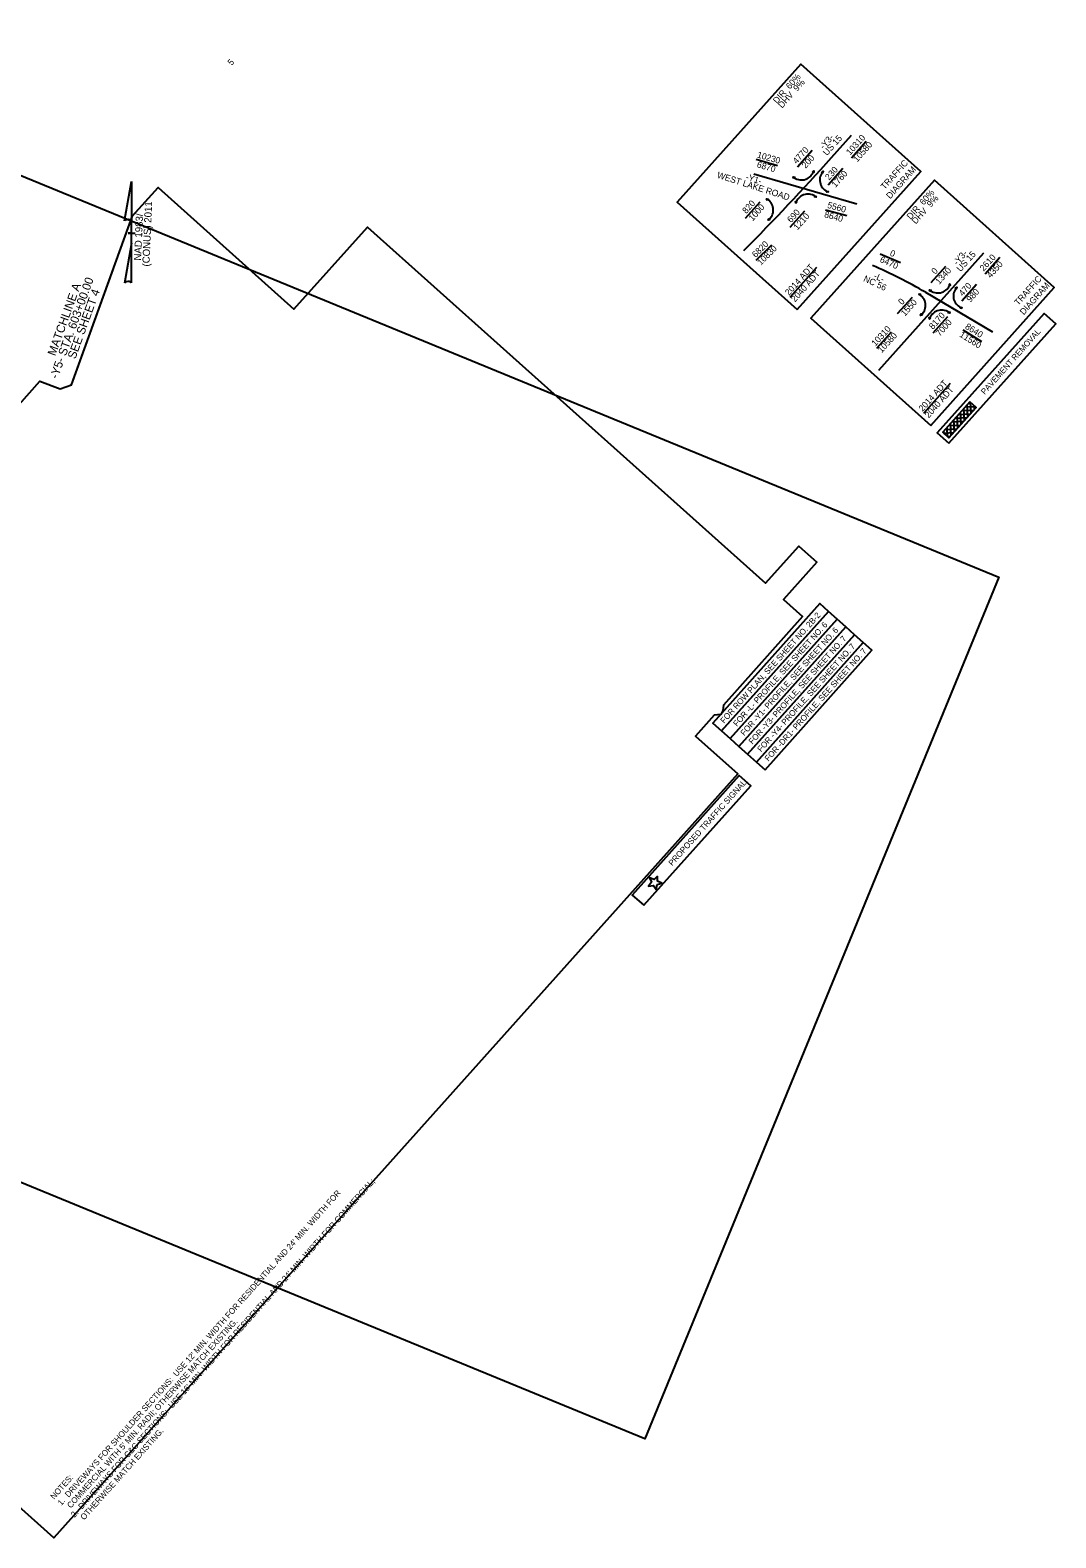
# Model space of a CAD drawing. Extents: x 2090929 to 2092987, y 862751 to 864596.
# Drawn here: x 2091776 to 2092987, y 862816 to 864596 of the extents above; entities that cross this region are included whole.
import ezdxf

# ---------------------------------------------------------------- set-up
doc = ezdxf.new("R2010")
doc.units = 0
for name, color, linetype in [('Matchline', 7, 'Continuous'), ('Matchline Text', 7, 'Continuous'), ('Prop DSN Text', 7, 'Continuous'), ('Prop Grid Mask', 7, 'Continuous'), ('Prop Hatching', 7, 'Continuous'), ('Prop Horizontal Alignment', 7, 'Continuous'), ('Prop North Arrow for Plan Sheets CELL', 7, 'Continuous'), ('Prop North Arrow NAD83 for Plan Sheets CELL', 7, 'Continuous'), ('Prop PHM Traffic Signal CELL', 7, 'Continuous'), ('Scratch_Level_6', 7, 'Continuous'), ('Sheet Clip Boundary CELL', 7, 'Continuous'), ('Sheet Data Field CELL', 7, 'Continuous')]:
    doc.layers.add(name, color=color, linetype=linetype)

msp = doc.modelspace()

# ---------------------------------------------------------------- linework, layer by layer
at = {"layer": 'Matchline'}
msp.add_line((2091824.5, 864177.1), (2091873.9, 864313.4), dxfattribs=at)
at = {"layer": 'Prop DSN Text'}
for p, q in [((2092681.5, 864434.6), (2092698.9, 864454)), ((2092745.3, 864445.2), (2092762.7, 864464.6)), ((2092633, 864443.5), (2092658, 864436.2)), ((2092718, 864413.3), (2092735.3, 864432.7)), ((2092620.1, 864373.7), (2092637.5, 864393.1)), ((2092673, 864363.1), (2092690.4, 864382.5)), ((2092714.9, 864383.7), (2092740, 864376.8)), ((2092632.8, 864324.1), (2092651.2, 864342.5)), ((2092779.3, 864331.7), (2092803.2, 864321.3)), ((2092903.1, 864308.3), (2092920.5, 864327.7)), ((2092673, 864280.7), (2092704.5, 864315.9)), ((2092839.3, 864297.7), (2092856.7, 864317.1)), ((2092875.7, 864276.4), (2092893.1, 864295.8)), ((2092799.9, 864261.3), (2092817.3, 864280.7)), ((2092841.8, 864238.4), (2092859.2, 864257.9)), ((2092775.2, 864220.5), (2092792.8, 864239.7)), ((2092876.8, 864242.1), (2092898.8, 864228.2)), ((2092830.7, 864143.7), (2092862.2, 864178.9))]:
    msp.add_line(p, q, dxfattribs=at)
for points in [[(2092681.2, 864266.1), (2092827.1, 864429.1), (2092685.5, 864555.7), (2092539.7, 864392.8)], [(2092839, 864129.1), (2092984.8, 864292.1), (2092843.3, 864418.8), (2092697.4, 864255.8)]]:
    msp.add_lwpolyline(points, close=True, dxfattribs=at)
for points in [[(2092677.3, 864420.8), (2092676.5, 864422.6), (2092678.5, 864422.3), (2092677.9, 864421.6), (2092677.3, 864420.8)], [(2092699.3, 864428.3), (2092700.8, 864429.6), (2092701.1, 864427.6), (2092700.2, 864428), (2092699.3, 864428.3)], [(2092710.2, 864428.5), (2092712, 864429.2), (2092711.6, 864427.3), (2092710.9, 864427.9), (2092710.2, 864428.5)], [(2092646.1, 864394.8), (2092645.1, 864396.5), (2092647.1, 864396.4), (2092646.6, 864395.6), (2092646.1, 864394.8)], [(2092703, 864400.4), (2092703.8, 864398.6), (2092701.8, 864398.9), (2092702.4, 864399.7), (2092703, 864400.4)], [(2092717, 864406.3), (2092718.3, 864404.8), (2092716.3, 864404.5), (2092716.7, 864405.4), (2092717, 864406.3)], [(2092681, 864392.7), (2092679.6, 864391.4), (2092679.3, 864393.4), (2092680.2, 864393), (2092681, 864392.7)], [(2092649.1, 864371.8), (2092647.2, 864371.4), (2092647.9, 864373.2), (2092648.5, 864372.5), (2092649.1, 864371.8)], [(2092838.2, 864287.4), (2092837.5, 864289.2), (2092839.4, 864288.9), (2092838.8, 864288.1), (2092838.2, 864287.4)], [(2092860.3, 864294.9), (2092861.7, 864296.2), (2092862, 864294.2), (2092861.1, 864294.5), (2092860.3, 864294.9)], [(2092867.9, 864291.5), (2092869.7, 864292.2), (2092869.4, 864290.3), (2092868.6, 864290.9), (2092867.9, 864291.5)], [(2092825.9, 864282.5), (2092824.9, 864284.2), (2092826.9, 864284.1), (2092826.4, 864283.3), (2092825.9, 864282.5)], [(2092828.9, 864259.4), (2092827, 864259), (2092827.7, 864260.8), (2092828.3, 864260.1), (2092828.9, 864259.4)], [(2092838.8, 864255.8), (2092837.4, 864254.5), (2092837, 864256.4), (2092837.9, 864256.1), (2092838.8, 864255.8)], [(2092860.8, 864263.5), (2092861.5, 864261.7), (2092859.6, 864262), (2092860.2, 864262.7), (2092860.8, 864263.5)], [(2092874.8, 864269.3), (2092876, 864267.8), (2092874.1, 864267.6), (2092874.5, 864268.4), (2092874.8, 864269.3)]]:
    msp.add_lwpolyline(points, dxfattribs=at)
for centre, start, end in [((2092686.4, 864433.9), 235.2927, 343.3275), ((2092723, 864419), 143.732, 251.7668), ((2092638.1, 864383.3), 313.9568, 61.9916), ((2092694, 864387.3), 55.8494, 163.8841), ((2092847.4, 864300.5), 235.2927, 343.3275), ((2092880.7, 864282), 143.732, 251.7668), ((2092817.9, 864270.9), 313.9568, 61.9916), ((2092851.8, 864250.3), 55.8494, 163.8841)]:
    msp.add_arc(centre, 15, start, end, dxfattribs=at)
at = {"layer": 'Prop Grid Mask'}
for points in [[(2092860.4, 864108), (2092986.7, 864249.1), (2092973, 864261.3), (2092846.7, 864120.2)], [(2092885.2, 864156.8), (2092853.2, 864121), (2092860.5, 864114.4), (2092892.5, 864150.2)], [(2092592, 863768.4), (2092718.3, 863909.5), (2092708.1, 863918.7), (2092581.8, 863777.6)], [(2092602.3, 863759.3), (2092728.6, 863900.4), (2092718.3, 863909.5), (2092592, 863768.4)], [(2092612.5, 863750.1), (2092738.8, 863891.2), (2092728.6, 863900.4), (2092602.3, 863759.3)], [(2092622.8, 863740.9), (2092749.1, 863882), (2092738.8, 863891.2), (2092612.5, 863750.1)], [(2092633.1, 863731.7), (2092759.3, 863872.8), (2092749.1, 863882), (2092622.8, 863740.9)], [(2092643.3, 863722.6), (2092769.6, 863863.7), (2092759.3, 863872.8), (2092633.1, 863731.7)], [(2092500.1, 863562.5), (2092626.4, 863703.6), (2092612.9, 863715.7), (2092486.6, 863574.6)]]:
    msp.add_lwpolyline(points, close=True, dxfattribs=at)
at = {"layer": 'Prop Hatching'}
for p, q in [((2092876, 864146.6), (2092889.9, 864147.3)), ((2092878.9, 864135), (2092878.1, 864148.9)), ((2092880, 864151), (2092891, 864151.6)), ((2092882.8, 864139.4), (2092882.1, 864153.3)), ((2092883.9, 864155.4), (2092886.6, 864155.6)), ((2092886.8, 864143.8), (2092886.1, 864156)), ((2092890.8, 864148.3), (2092890.6, 864152)), ((2092860.2, 864128.9), (2092874.1, 864129.6)), ((2092863, 864117.3), (2092862.3, 864131.2)), ((2092864.1, 864133.3), (2092878, 864134)), ((2092867, 864121.7), (2092866.2, 864135.6)), ((2092868.1, 864137.7), (2092882, 864138.5)), ((2092871, 864126.1), (2092870.2, 864140.1)), ((2092872, 864142.1), (2092886, 864142.9)), ((2092874.9, 864130.6), (2092874.1, 864144.5)), ((2092854.2, 864120.1), (2092866.2, 864120.8)), ((2092854.5, 864119.8), (2092854.3, 864122.3)), ((2092856.2, 864124.4), (2092870.1, 864125.2)), ((2092858.9, 864115.9), (2092858.3, 864126.8)), ((2092858.6, 864116.1), (2092862.2, 864116.3))]:
    msp.add_line(p, q, dxfattribs=at)
at = {"layer": 'Prop Horizontal Alignment'}
for p, q in [((2092721.8, 864445.5), (2092745.6, 864472)), ((2092630.2, 864426.3), (2092751.9, 864390.6)), ((2092777.6, 864194.3), (2092901.5, 864332.9)), ((2092832.7, 864286.3), (2092911.7, 864239.6))]:
    msp.add_line(p, q, dxfattribs=at)
for centre, radius, start, end in [((2090486.4, 866446.2), 3000, 315.2914, 318.1706), ((2092561.6, 863827.4), 533, 59.4206, 66.9805)]:
    msp.add_arc(centre, radius, start, end, dxfattribs=at)
at = {"layer": 'Prop North Arrow for Plan Sheets CELL'}
for p, q in [((2091887.2, 864370.7), (2091895.4, 864417.1)), ((2091895.4, 864417.1), (2091895.4, 864417.1)), ((2091895.4, 864417.1), (2091895.4, 864417.1)), ((2091895.4, 864417.1), (2091895.4, 864369.3)), ((2091895.4, 864344.5), (2091895.4, 864370.7)), ((2091895.4, 864369.3), (2091895.4, 864370.6)), ((2091895.4, 864344.5), (2091887.1, 864297.2)), ((2091895, 864356.1), (2091891.4, 864356.1)), ((2091891.4, 864356.1), (2091891.4, 864356.1)), ((2091891.5, 864356.1), (2091899.5, 864356.1)), ((2091895.5, 864297.4), (2091895.4, 864344.5))]:
    msp.add_line(p, q, dxfattribs=at)
for centre, start_param, end_param in [((2091891.3, 864370.2), 0.216388, 2.908219), ((2091891.3, 864297), 0.201328, 3.141593)]:
    msp.add_ellipse(centre, major_axis=(4.23, -0.03), ratio=0.461098, start_param=start_param, end_param=end_param, dxfattribs=at)
at = {"layer": 'Prop PHM Traffic Signal CELL'}
msp.add_lwpolyline([(2092516.5, 863597.1), (2092512.3, 863593), (2092506.8, 863595), (2092509.4, 863589.8), (2092505.8, 863585.2), (2092511.6, 863586), (2092514.8, 863581.2), (2092515.8, 863587), (2092521.4, 863588.5), (2092516.2, 863591.2)], close=True, dxfattribs=at)
at = {"layer": 'Scratch_Level_6'}
msp.add_lwpolyline([(2091346.9, 864595.8), (2092919.5, 863950), (2092501.6, 862932.5), (2090929.1, 863578.3)], close=True, dxfattribs=at)
at = {"layer": 'Sheet Clip Boundary CELL'}
msp.add_lwpolyline([(2091698.1, 864081.6), (2091787.3, 864181.2), (2091811.1, 864172.4), (2091824.5, 864177.1), (2091896.7, 864376.5), (2091926.7, 864410), (2092087.2, 864266.3), (2092174, 864363.2), (2092643.8, 863942.7), (2092683.2, 863986.7), (2092704.4, 863967.8), (2092665, 863923.7), (2092687.7, 863903.4), (2092594.2, 863799), (2092593.5, 863792.6), (2092591, 863787.9), (2092583.3, 863786.9), (2092561.4, 863762.3), (2092611.2, 863717.7), (2091803.8, 862815.7), (2091354.2, 863218.1)], dxfattribs=at)

# ---------------------------------------------------------------- texts
at = {"layer": 'Matchline Text'}
for s, p in [('MATCHLINE A', (2091805.3, 864210.5)), ('-Y5- STA. 603+00.00', (2091808, 864183.3)), ('SEE SHEET 4', (2091829, 864206.8))]:
    msp.add_text(s, height=10, rotation=70.1116, dxfattribs=at).set_placement(p)
at = {"layer": 'Prop DSN Text'}
for s, height, rotation, p in [('DIR  60%', 7.5, 48.1706, (2092657.5, 864508.5)), ('DHV  9%', 7.5, 48.1706, (2092663.5, 864503.1)), ('-Y3-', 7.5, 48.1706, (2092712.5, 864454.7)), ('US 15', 7.5, 48.1706, (2092716.4, 864447)), ('10310', 7.5, 48.1706, (2092743.8, 864447.6)), ('10230', 7.5, 343.7474, (2092633.4, 864445.6)), ('4770', 7.5, 48.1706, (2092680.7, 864437.3)), ('10580', 7.5, 48.1706, (2092752.1, 864439.4)), ('6870', 7.5, 343.7474, (2092633.1, 864434.1)), ('200', 7.5, 48.1706, (2092691.3, 864432)), ('230', 7.5, 48.1706, (2092719, 864418.1)), ('TRAFFIC', 7.5, 48.1706, (2092784.6, 864407)), ('DIAGRAM', 7.5, 48.1706, (2092791.1, 864396)), ('WEST LAKE ROAD', 7.5, 342.291, (2092586.1, 864421.7)), ('-Y1-', 7.5, 342.291, (2092619.9, 864419.4)), ('1760', 7.5, 48.1706, (2092726.5, 864409.4)), ('DIR  60%', 7.5, 48.1706, (2092815.3, 864371.6)), ('DHV  9%', 7.5, 48.1706, (2092821.3, 864366.2)), ('820', 7.5, 48.1706, (2092621.2, 864378.5)), ('1000', 7.5, 48.1706, (2092628.7, 864369.8)), ('690', 7.5, 48.1706, (2092674.1, 864367.9)), ('1210', 7.5, 48.1706, (2092681.6, 864359.2)), ('8640', 7.5, 344.6116, (2092712.7, 864375.1)), ('5560', 7.5, 344.6116, (2092716.3, 864386.1)), ('6820', 7.5, 44.9709, (2092632.3, 864326.7)), ('10830', 7.5, 44.9709, (2092638.4, 864317.6)), ('6470', 7.5, 336.3443, (2092778.2, 864322.4)), ('0', 7.5, 336.3443, (2092790, 864329.9)), ('-Y3-', 7.5, 48.1706, (2092870.2, 864317.8)), ('US 15', 7.5, 48.1706, (2092874.2, 864310)), ('2610', 7.5, 48.1706, (2092901.5, 864310.6)), ('2014 ADT', 7.5, 48.1706, (2092671.7, 864281.9)), ('2040 ADT', 7.5, 48.1706, (2092678.8, 864274.3)), ('NC 56', 7.5, 334.9874, (2092758.8, 864299.8)), ('-L-', 7.5, 334.9874, (2092771, 864303.1)), ('0', 7.5, 48.1706, (2092844.4, 864307)), ('1340', 7.5, 48.1706, (2092849, 864295)), ('4350', 7.5, 48.1706, (2092909.8, 864302.5)), ('470', 7.5, 48.1706, (2092876.8, 864281.1)), ('980', 7.5, 48.1706, (2092885.8, 864274)), ('TRAFFIC', 7.5, 48.1706, (2092942.4, 864270.1)), ('DIAGRAM', 7.5, 48.1706, (2092948.8, 864259)), ('0', 7.5, 48.1706, (2092805.2, 864270.9)), ('1550', 7.5, 48.1706, (2092808.5, 864257.4)), ('8170', 7.5, 48.1706, (2092841.6, 864241.9)), ('7000', 7.5, 48.1706, (2092849.7, 864233.7)), ('10310', 7.5, 47.4999, (2092773.6, 864222)), ('10580', 7.5, 47.4999, (2092781.1, 864214.2)), ('11560', 7.5, 327.7858, (2092872.2, 864234.5)), ('8640', 7.5, 327.7858, (2092878.8, 864244)), ('PAVEMENT REMOVAL', 7, 48.1706, (2092902.7, 864165)), ('2014 ADT', 7.5, 48.1706, (2092829.4, 864144.9)), ('2040 ADT', 7.5, 48.1706, (2092836.6, 864137.3)), ('FOR ROW PLAN, SEE SHEET NO. 2B-2', 7, 48.1706, (2092595, 863776.7)), ('FOR -L- PROFILE, SEE SHEET NO. 6', 7, 48.1706, (2092610.2, 863773.1)), ('FOR -Y1- PROFILE, SEE SHEET NO. 6', 7, 48.1706, (2092618.8, 863762.1)), ('FOR -Y3- PROFILE, SEE SHEET NO. 7', 7, 48.1706, (2092628.4, 863752.1)), ('FOR -Y4- PROFILE, SEE SHEET NO. 7', 7, 48.1706, (2092638.7, 863743)), ('FOR -DR1- PROFILE, SEE SHEET NO. 7', 7, 48.1706, (2092647.3, 863732)), ('PROPOSED TRAFFIC SIGNAL', 7, 48.1706, (2092533.8, 863608.5)), ("2.  DRIVEWAYS FOR C&G SECTIONS:  USE 16' MIN. WIDTH FOR RESIDENTIAL AND 24' MIN. WIDTH FOR COMMERCIAL;", 7, 48.1706, (2091828.2, 862839.2)), ("1.  DRIVEWAYS FOR SHOULDER SECTIONS:  USE 12' MIN. WIDTH FOR RESIDENTIAL AND 24' MIN. WIDTH FOR", 7, 48.1706, (2091812.5, 862853.2)), ("  COMMERCIAL WITH 5' MIN. RADII; OTHERWISE MATCH EXISTING.", 7, 48.1706, (2091820.3, 862846.2)), ('  OTHERWISE MATCH EXISTING.', 7, 48.1706, (2091836, 862832.2)), ('NOTES:', 7, 48.1706, (2091804, 862860.5))]:
    msp.add_text(s, height=height, rotation=rotation, dxfattribs=at).set_placement(p)
at = {"layer": 'Prop North Arrow NAD83 for Plan Sheets CELL'}
for s, p in [('NAD 1983/ ', (2091906.7, 864323.6)), ('(CONUS) 2011', (2091916.5, 864316.6))]:
    msp.add_text(s, height=8.5, rotation=87.5603, dxfattribs=at).set_placement(p)
at = {"layer": 'Sheet Data Field CELL'}
msp.add_text('5', height=7.5, rotation=48.1706, dxfattribs=at).set_placement((2092013.6, 864553.5))

doc.saveas('drawing.dxf')
